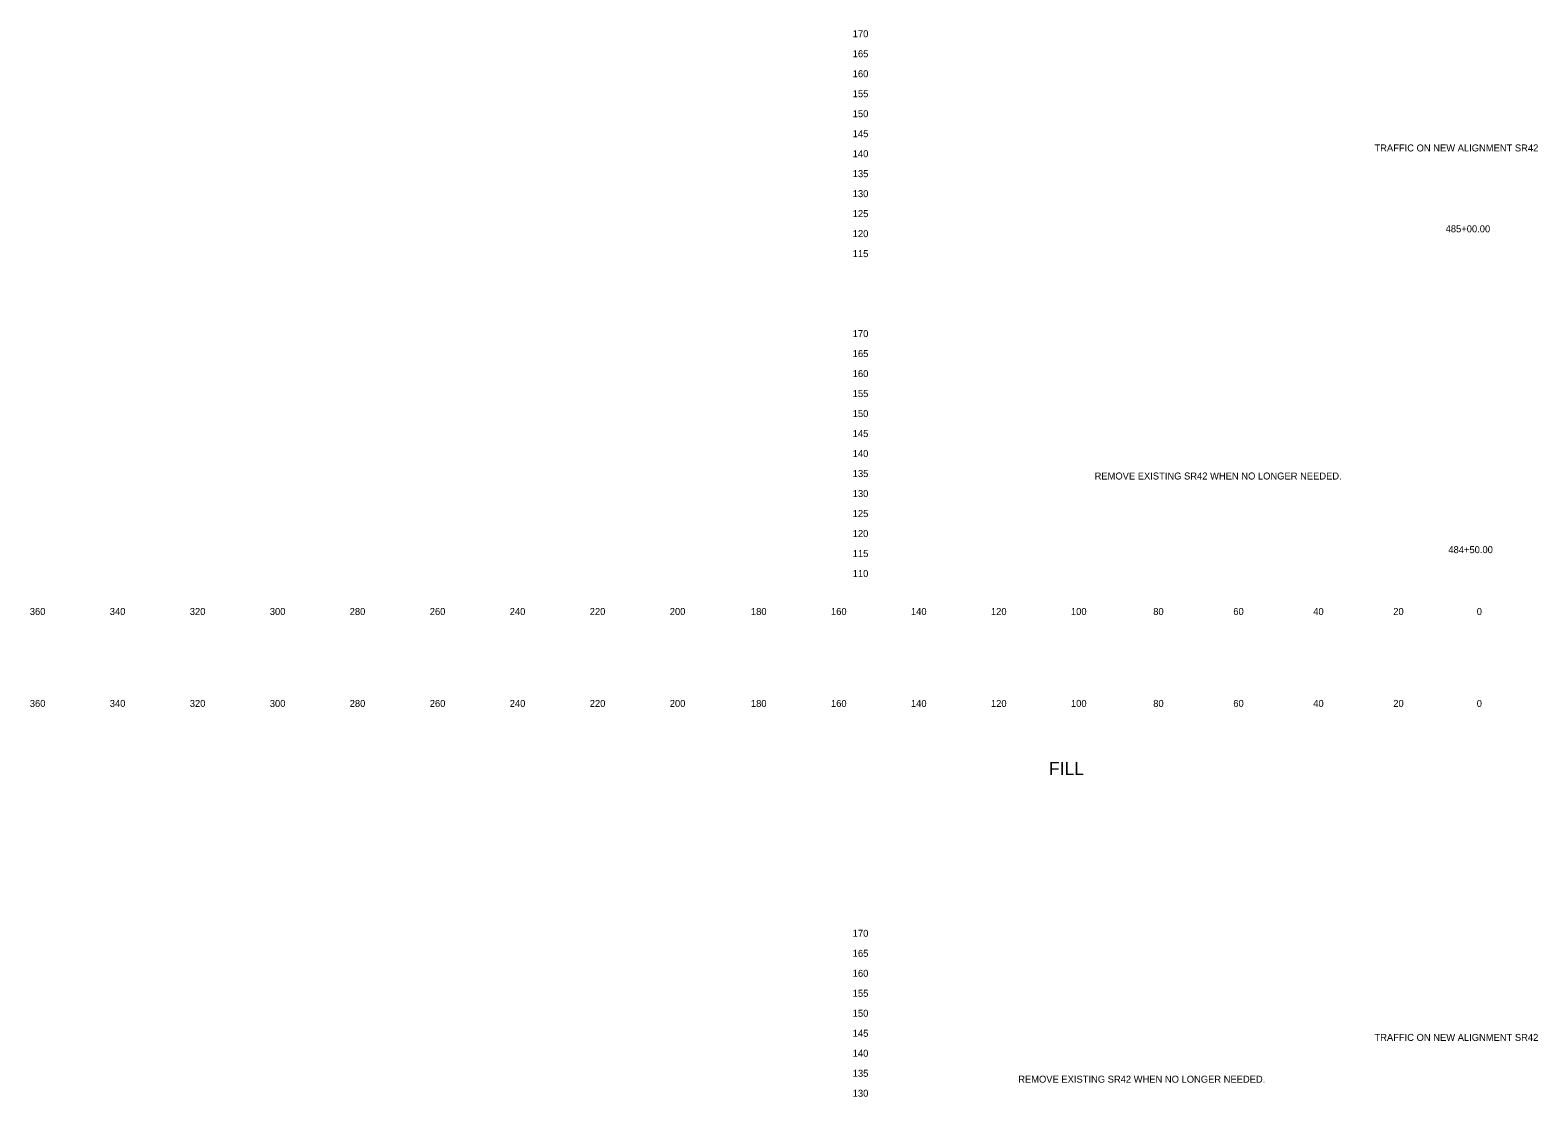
# Model space of a CAD drawing. Extents: x 21281 to 22024, y 6472 to 15208.
# Drawn here: x 21280.5 to 21657.4, y 13024.8 to 13291.6 of the extents above; entities that cross this region are included whole.
import ezdxf

# ---------------------------------------------------------------- set-up
doc = ezdxf.new("R2010")
doc.units = 0
for name, color, linetype in [('XS_SHEET_LABELS_ELEVATION', 7, 'Continuous'), ('XS_SHEET_LABELS_OFFSET', 7, 'Continuous'), ('XS_SHEET_LABELS_STATION', 7, 'Continuous')]:
    doc.layers.add(name, color=color, linetype=linetype)

msp = doc.modelspace()

# ---------------------------------------------------------------- texts
at = {"layer": 'XS_SHEET_LABELS_ELEVATION'}
for s, p in [('  170  ', (21484.84, 13289.84)), ('  165  ', (21484.84, 13284.84)), ('  160  ', (21484.84, 13279.84)), ('  155  ', (21484.84, 13274.84)), ('  150  ', (21484.84, 13269.84)), ('  145  ', (21484.84, 13264.84)), ('  140  ', (21484.84, 13259.84)), ('  135  ', (21484.84, 13254.84)), ('  130  ', (21484.84, 13249.84)), ('  125  ', (21484.84, 13244.84)), ('  120  ', (21484.84, 13239.84)), ('  115  ', (21484.84, 13234.84)), ('  170  ', (21484.84, 13214.84)), ('  165  ', (21484.84, 13209.84)), ('  160  ', (21484.84, 13204.84)), ('  155  ', (21484.84, 13199.84)), ('  150  ', (21484.84, 13194.84)), ('  145  ', (21484.84, 13189.84)), ('  140  ', (21484.84, 13184.84)), ('  135  ', (21484.84, 13179.84)), ('  130  ', (21484.84, 13174.84)), ('  125  ', (21484.84, 13169.84)), ('  120  ', (21484.84, 13164.84)), ('  115  ', (21484.84, 13159.84)), ('  110  ', (21484.84, 13154.84)), ('  170  ', (21484.84, 13064.84)), ('  165  ', (21484.84, 13059.84)), ('  160  ', (21484.84, 13054.84)), ('  155  ', (21484.84, 13049.84)), ('  150  ', (21484.84, 13044.84)), ('  145  ', (21484.84, 13039.84)), ('  140  ', (21484.84, 13034.84)), ('  135  ', (21484.84, 13029.84)), ('  130  ', (21484.84, 13024.84))]:
    msp.add_text(s, height=1.75, dxfattribs=at).set_placement(p)
at = {"layer": 'XS_SHEET_LABELS_OFFSET'}
for s, height, p in [('  360  ', 1.75, (21279.14, 13145.34)), ('  340  ', 1.75, (21299.13, 13145.34)), ('  320  ', 1.75, (21319.13, 13145.34)), ('  300  ', 1.75, (21339.13, 13145.34)), ('  280  ', 1.75, (21359.1, 13145.34)), ('  260  ', 1.75, (21379.11, 13145.34)), ('  240  ', 1.75, (21399.1, 13145.34)), ('  220  ', 1.75, (21419.1, 13145.34)), ('  200  ', 1.75, (21439.1, 13145.34)), ('  180  ', 1.75, (21459.39, 13145.34)), ('  160  ', 1.75, (21479.4, 13145.34)), ('  140  ', 1.75, (21499.39, 13145.34)), ('  120  ', 1.75, (21519.39, 13145.34)), ('  100  ', 1.75, (21539.39, 13145.34)), ('  80  ', 1.75, (21559.95, 13145.34)), ('  60  ', 1.75, (21579.97, 13145.34)), ('  40  ', 1.75, (21599.95, 13145.34)), ('  20  ', 1.75, (21619.95, 13145.34)), ('  0  ', 1.75, (21640.81, 13145.34)), ('  0  ', 1.75, (21640.81, 13145.34)), ('  360  ', 1.75, (21279.14, 13122.34)), ('  340  ', 1.75, (21299.13, 13122.34)), ('  320  ', 1.75, (21319.13, 13122.34)), ('  300  ', 1.75, (21339.13, 13122.34)), ('  280  ', 1.75, (21359.1, 13122.34)), ('  260  ', 1.75, (21379.11, 13122.34)), ('  240  ', 1.75, (21399.1, 13122.34)), ('  220  ', 1.75, (21419.1, 13122.34)), ('  200  ', 1.75, (21439.1, 13122.34)), ('  180  ', 1.75, (21459.39, 13122.34)), ('  160  ', 1.75, (21479.4, 13122.34)), ('  140  ', 1.75, (21499.39, 13122.34)), ('  120  ', 1.75, (21519.39, 13122.34)), ('  100  ', 1.75, (21539.39, 13122.34)), ('  80  ', 1.75, (21559.95, 13122.34)), ('  60  ', 1.75, (21579.97, 13122.34)), ('  40  ', 1.75, (21599.95, 13122.34)), ('  20  ', 1.75, (21619.95, 13122.34)), ('  0  ', 1.75, (21640.81, 13122.34)), ('  0  ', 1.75, (21640.81, 13122.34)), ('FILL', 3.273, (21535.18, 13105.29))]:
    msp.add_text(s, height=height, dxfattribs=at).set_placement(p)
at = {"layer": 'XS_SHEET_LABELS_STATION'}
for s, p in [('TRAFFIC ON NEW ALIGNMENT SR42', (21616.55, 13261.27)), ('  485+00.00  ', (21633.04, 13241.04)), ('REMOVE EXISTING SR42 WHEN NO LONGER NEEDED.', (21546.59, 13179.22)), ('  484+50.00  ', (21633.72, 13160.8)), ('TRAFFIC ON NEW ALIGNMENT SR42', (21616.55, 13038.81)), ('REMOVE EXISTING SR42 WHEN NO LONGER NEEDED.', (21527.5, 13028.35))]:
    msp.add_text(s, height=1.75, dxfattribs=at).set_placement(p)

doc.saveas('drawing.dxf')
